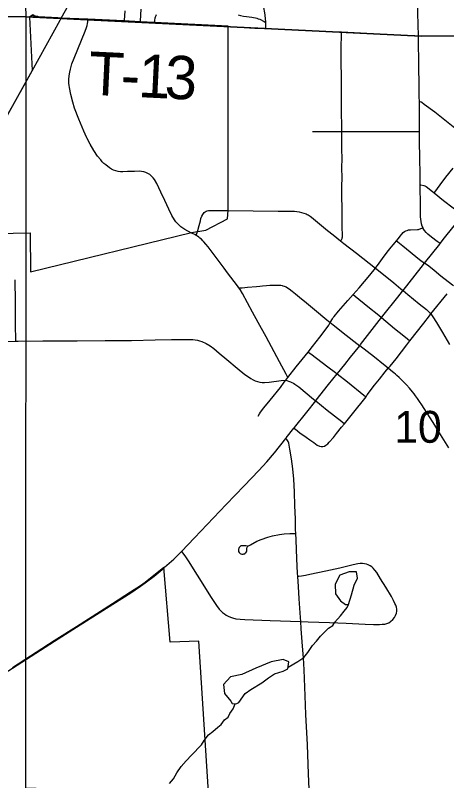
# Model space of a CAD drawing. Extents: x 0 to 34, y -5 to 22.
# Drawn here: x 3.09 to 3.656, y 14.615 to 15.62 of the extents above; entities that cross this region are included whole.
import ezdxf

# ---------------------------------------------------------------- set-up
doc = ezdxf.new("R2010")
doc.units = 0
for name, color, linetype in [('GM_X_City_Street', 7, 'Continuous'), ('GM_X_Corporation', 7, 'Continuous'), ('GM_X_County_Road', 7, 'Continuous'), ('GM_X_Minor_Lake', 7, 'Continuous'), ('GM_X_Minor_River', 7, 'Continuous'), ('GM_X_Section', 7, 'Continuous'), ('GM_X_Section_Text', 7, 'Continuous'), ('GM_X_State_Route', 7, 'Continuous'), ('GM_X_Township_Road', 7, 'Continuous'), ('GM_X_Township_Road_Text', 7, 'Continuous')]:
    doc.layers.add(name, color=color, linetype=linetype)

msp = doc.modelspace()

# ---------------------------------------------------------------- linework, layer by layer
at = {"layer": 'GM_X_City_Street'}
for points in [[(3.4191, 15.6022), (3.4191, 15.6043), (3.4191, 15.6081), (3.419, 15.6103), (3.419, 15.6115), (3.4187, 15.6143), (3.4181, 15.6203), (3.4162, 15.6325), (3.4142, 15.6442), (3.4121, 15.6568), (3.4104, 15.6677), (3.4099, 15.6736), (3.4097, 15.6784)], [(3.2548, 15.6277), (3.2543, 15.6125), (3.2542, 15.6106)], [(3.2334, 15.6117), (3.2334, 15.6128), (3.2342, 15.6256)], [(3.2733, 15.6097), (3.2734, 15.6111), (3.2735, 15.6128), (3.274, 15.6164), (3.2743, 15.6177), (3.275, 15.6195), (3.2756, 15.6205)], [(3.3827, 15.62), (3.386, 15.6192), (3.3896, 15.6185), (3.3936, 15.618), (3.3972, 15.6176), (3.4009, 15.6171), (3.4029, 15.6167), (3.4056, 15.6162), (3.4072, 15.6157), (3.4092, 15.6151), (3.4111, 15.6143), (3.4168, 15.6114), (3.419, 15.6103)], [(3.5173, 15.3235), (3.5177, 15.3241), (3.5184, 15.3251), (3.5188, 15.3258), (3.5191, 15.3267), (3.5193, 15.3278), (3.5195, 15.329), (3.5194, 15.344), (3.5192, 15.3673), (3.519, 15.3808), (3.5189, 15.395), (3.5191, 15.4069), (3.5189, 15.4191), (3.5191, 15.4323), (3.519, 15.4436), (3.5188, 15.4552), (3.5188, 15.4651), (3.5188, 15.4671), (3.5187, 15.476), (3.5186, 15.4909), (3.5185, 15.5064), (3.5183, 15.5236), (3.5182, 15.5435), (3.5181, 15.5528), (3.518, 15.5713), (3.5181, 15.5775), (3.5184, 15.5939), (3.5185, 15.5977)], [(3.6206, 15.5065), (3.6214, 15.5064), (3.6224, 15.5062), (3.6231, 15.506), (3.6239, 15.5055), (3.6271, 15.5031), (3.6407, 15.4928), (3.6651, 15.4737), (3.6741, 15.4666), (3.6828, 15.4597), (3.6922, 15.4523), (3.6965, 15.449), (3.7073, 15.4403), (3.7212, 15.429), (3.7284, 15.4232), (3.7294, 15.4224)], [(3.4803, 15.4673), (3.4941, 15.4673), (3.5145, 15.4671), (3.5188, 15.4671), (3.5244, 15.4671), (3.5477, 15.4672), (3.5728, 15.4672), (3.5932, 15.4671), (3.6119, 15.4672), (3.6165, 15.4671), (3.6209, 15.4671)], [(3.64, 15.3866), (3.6407, 15.3876), (3.6477, 15.3972), (3.6555, 15.4072), (3.6651, 15.4191)], [(3.6217, 15.3972), (3.6226, 15.397), (3.6266, 15.3963), (3.6276, 15.396), (3.6287, 15.3956), (3.6296, 15.3951), (3.6377, 15.3885), (3.64, 15.3866), (3.6524, 15.3765), (3.6651, 15.3668), (3.6693, 15.3633), (3.6758, 15.3582), (3.6773, 15.357)], [(3.3696, 15.3635), (3.4351, 15.3628), (3.4506, 15.3626), (3.4568, 15.3624), (3.463, 15.3617), (3.466, 15.361), (3.469, 15.3601), (3.4719, 15.3591), (3.4735, 15.3583), (3.4747, 15.3577), (3.4772, 15.356), (3.4788, 15.3548), (3.5002, 15.3373), (3.5073, 15.3315), (3.5173, 15.3235), (3.5215, 15.3202), (3.538, 15.3073), (3.5629, 15.2877), (3.5646, 15.2864), (3.5869, 15.2687), (3.5964, 15.2609), (3.5992, 15.2585)], [(3.5629, 15.2877), (3.5636, 15.2888), (3.5656, 15.2915), (3.5745, 15.3036), (3.58, 15.3109), (3.5838, 15.3155), (3.5865, 15.3187), (3.5885, 15.3209), (3.5907, 15.3236), (3.5931, 15.3267), (3.5955, 15.3299), (3.5977, 15.3326), (3.5995, 15.3346), (3.6013, 15.336), (3.6029, 15.3368), (3.6046, 15.3374), (3.6065, 15.3379), (3.6088, 15.3382), (3.618, 15.3384), (3.6196, 15.3386), (3.6225, 15.3397), (3.6254, 15.3407)], [(3.5907, 15.3236), (3.5924, 15.3223), (3.5991, 15.317), (3.6208, 15.2993), (3.6274, 15.2942)], [(3.5037, 15.2165), (3.5065, 15.2213), (3.5076, 15.2229), (3.5086, 15.2243), (3.5145, 15.2314), (3.5267, 15.2452), (3.5339, 15.2533), (3.5417, 15.2622), (3.5555, 15.2786), (3.5629, 15.2877)], [(3.0908, 15.1919), (3.0907, 15.1974), (3.0905, 15.2095), (3.0904, 15.243), (3.0902, 15.2727)], [(3.3838, 15.2619), (3.3882, 15.2622), (3.3948, 15.2628), (3.4067, 15.2639), (3.4111, 15.2644), (3.4147, 15.2647), (3.42, 15.2652), (3.4242, 15.2655), (3.4265, 15.2656), (3.4284, 15.2656), (3.4311, 15.2657), (3.4343, 15.2657), (3.4376, 15.2655), (3.4389, 15.2654), (3.4403, 15.2651), (3.4415, 15.2648), (3.443, 15.2643), (3.4443, 15.2638), (3.4456, 15.2631), (3.4475, 15.2621), (3.4497, 15.2607), (3.4535, 15.2577), (3.458, 15.2541), (3.4633, 15.2497), (3.4723, 15.2422), (3.4829, 15.2335), (3.4992, 15.2202), (3.5037, 15.2165), (3.5094, 15.212), (3.5207, 15.2029), (3.5423, 15.1859)], [(3.5796, 15.1566), (3.5823, 15.1594), (3.5901, 15.1689), (3.604, 15.1871), (3.6081, 15.1924), (3.6263, 15.2157), (3.6337, 15.2252), (3.6358, 15.2277), (3.6569, 15.2543)], [(3.5992, 15.2585), (3.6055, 15.2534), (3.6204, 15.2412), (3.6299, 15.2335), (3.6328, 15.2309), (3.635, 15.2287), (3.6358, 15.2277), (3.6366, 15.2267), (3.6382, 15.2241), (3.6432, 15.2164), (3.6511, 15.2032), (3.6602, 15.1875)], [(3.5339, 15.2533), (3.5365, 15.251), (3.5529, 15.2373), (3.5673, 15.2261), (3.5711, 15.2231)], [(3.4091, 15.0938), (3.4107, 15.0969), (3.4119, 15.0987), (3.4164, 15.1044), (3.4247, 15.1147), (3.4382, 15.1313), (3.4433, 15.1382), (3.4453, 15.1407), (3.4481, 15.1443), (3.459, 15.1582), (3.4708, 15.1727), (3.4748, 15.1778), (3.4804, 15.185), (3.4898, 15.1974), (3.5007, 15.2117), (3.5018, 15.2132), (3.5026, 15.2146), (3.5037, 15.2165)], [(3.5711, 15.2231), (3.5881, 15.2087), (3.6002, 15.1989), (3.605, 15.195), (3.6081, 15.1924)], [(3.4748, 15.1778), (3.4783, 15.1752), (3.5005, 15.1585), (3.5103, 15.1509), (3.5127, 15.149)], [(3.5224, 15.0837), (3.5365, 15.1012), (3.5473, 15.1148), (3.5506, 15.1192), (3.5522, 15.1214), (3.5619, 15.1341), (3.5682, 15.1423), (3.5755, 15.1518), (3.5796, 15.1566)], [(3.5127, 15.149), (3.5263, 15.1385), (3.5479, 15.1213), (3.5506, 15.1192)], [(3.4845, 15.1138), (3.4994, 15.1017), (3.5187, 15.0866), (3.5224, 15.0837)], [(3.456, 15.078), (3.4578, 15.0765), (3.4637, 15.0717), (3.4719, 15.066), (3.4769, 15.0626), (3.4819, 15.059), (3.4866, 15.0556), (3.4895, 15.0542), (3.4917, 15.0538), (3.4938, 15.0538), (3.4959, 15.0544), (3.498, 15.0556), (3.5003, 15.0573), (3.5024, 15.0594), (3.5079, 15.0658), (3.5117, 15.0708), (3.5185, 15.0791), (3.5224, 15.0837)], [(3.4766, 14.5941), (3.4752, 14.6244), (3.4736, 14.6624), (3.4717, 14.7021), (3.4708, 14.7269), (3.4692, 14.761), (3.4683, 14.7765), (3.4672, 14.792), (3.4656, 14.8148), (3.4649, 14.824), (3.4646, 14.8295), (3.4629, 14.8538), (3.4619, 14.87), (3.4611, 14.8832), (3.4608, 14.8878), (3.4599, 14.9065), (3.4587, 14.9313), (3.4583, 14.9397), (3.4581, 14.9451), (3.4578, 14.9591), (3.4573, 14.9759), (3.4567, 14.9945), (3.4557, 15.0109), (3.4544, 15.0245), (3.4527, 15.0376), (3.4506, 15.0505), (3.4491, 15.0581), (3.4487, 15.0593), (3.4482, 15.0606), (3.4475, 15.0616), (3.4465, 15.0628), (3.4451, 15.0644)], [(3.3949, 14.9229), (3.393, 14.9233), (3.3908, 14.9236), (3.389, 14.9237), (3.3877, 14.9236), (3.3863, 14.9233), (3.3854, 14.9227), (3.3846, 14.9219), (3.384, 14.9212), (3.3836, 14.9202), (3.3833, 14.9192), (3.3832, 14.9182), (3.3832, 14.9172), (3.3834, 14.916), (3.3839, 14.9149), (3.3845, 14.9141), (3.3854, 14.9134), (3.3863, 14.9129), (3.3874, 14.9126), (3.3885, 14.9125), (3.3895, 14.9126), (3.3904, 14.9128), (3.3913, 14.9132), (3.3919, 14.9137), (3.3928, 14.9145), (3.3936, 14.9156), (3.394, 14.9165), (3.3942, 14.9175), (3.3943, 14.9208), (3.3945, 14.9217), (3.3949, 14.9224), (3.3953, 14.923), (3.3988, 14.925), (3.4071, 14.9294), (3.4129, 14.9319), (3.4217, 14.935), (3.4278, 14.9366), (3.437, 14.9384), (3.4432, 14.9391), (3.4504, 14.9395), (3.4564, 14.9397), (3.4583, 14.9397)], [(3.3084, 14.916), (3.3127, 14.9102), (3.317, 14.904), (3.3291, 14.8848), (3.3475, 14.8559), (3.3543, 14.8454), (3.358, 14.8405), (3.3601, 14.8383), (3.3623, 14.8362), (3.3646, 14.8343), (3.3671, 14.8325), (3.3698, 14.831), (3.3725, 14.8298), (3.3754, 14.8289), (3.3798, 14.8278), (3.3854, 14.8271), (3.3914, 14.8269), (3.4248, 14.8254), (3.4649, 14.824), (3.4746, 14.8237), (3.5027, 14.8229), (3.5244, 14.8219), (3.5493, 14.8207), (3.5603, 14.8203), (3.5683, 14.8204), (3.5719, 14.8205), (3.5751, 14.8209), (3.5778, 14.8215), (3.5805, 14.8226), (3.5828, 14.8242), (3.5859, 14.8269), (3.5879, 14.8295), (3.5893, 14.8321), (3.5904, 14.835), (3.5909, 14.8376), (3.5909, 14.8402), (3.5904, 14.843), (3.5896, 14.8456), (3.5884, 14.848), (3.5866, 14.8519), (3.5839, 14.8569), (3.5764, 14.8691), (3.5695, 14.8804), (3.5646, 14.8884), (3.5623, 14.8915), (3.5598, 14.8944), (3.5581, 14.896), (3.5559, 14.8973), (3.5535, 14.8985), (3.5511, 14.8993), (3.5487, 14.8999), (3.5459, 14.9002), (3.5431, 14.9002), (3.5397, 14.9), (3.5337, 14.8986), (3.516, 14.8944), (3.498, 14.8903), (3.477, 14.8858), (3.4711, 14.8847), (3.4658, 14.8838), (3.4626, 14.8834), (3.4611, 14.8832)]]:
    msp.add_lwpolyline(points, dxfattribs=at)
msp.add_lwpolyline([(2.1, 15.6177), (2.1, 15.3638), (2.1133, 14.5841), (3.104, 14.6056), (3.1044, 15.6177)], close=True, dxfattribs=at)
at = {"layer": 'GM_X_Corporation'}
for points in [[(2.9981, 15.3319), (3.1097, 15.3342), (3.1101, 15.283), (3.3215, 15.3344), (3.3404, 15.3375), (3.3688, 15.3524), (3.3694, 15.3641), (3.3695, 15.6054), (3.2731, 15.6102), (3.254, 15.6112), (3.2327, 15.6123), (3.1852, 15.6144), (3.15, 15.6159), (3.146, 15.6163), (3.1208, 15.6177), (3.1203, 15.6177), (3.1198, 15.6178), (3.1188, 15.6179), (3.1165, 15.6184), (3.1156, 15.6187), (3.1147, 15.6191), (3.1131, 15.6201), (3.1088, 15.6173), (3.1122, 15.5472), (2.9904, 15.3289)], [(3.3438, 14.6005), (3.3313, 14.7985), (3.2934, 14.7972), (3.2852, 14.8952), (3.2722, 14.8844), (3.2605, 14.8754), (3.2544, 14.8712), (3.2415, 14.8626), (3.2179, 14.8475), (3.1705, 14.8173), (3.1414, 14.7989), (3.0864, 14.7636)]]:
    msp.add_lwpolyline(points, dxfattribs=at)
at = {"layer": 'GM_X_County_Road'}
for p, q in [((3.6274, 15.2942), (3.6473, 15.3192)), ((3.6473, 15.3192), (3.6479, 15.32)), ((3.5429, 15.1867), (3.5435, 15.1875)), ((3.3077, 14.9154), (3.3084, 14.916))]:
    msp.add_line(p, q, dxfattribs=at)
for points in [[(3.6193, 15.5928), (3.6173, 15.6675), (3.617, 15.6947)], [(3.6206, 15.5065), (3.6205, 15.5125), (3.6202, 15.5311), (3.62, 15.5496), (3.6198, 15.5588), (3.6194, 15.5833), (3.6193, 15.5928)], [(3.6209, 15.4671), (3.6208, 15.479), (3.6207, 15.4882), (3.6207, 15.5002), (3.6206, 15.5065)], [(3.6217, 15.3972), (3.6216, 15.4109), (3.6213, 15.4325), (3.6209, 15.4542), (3.6209, 15.4671)], [(3.6254, 15.3407), (3.6244, 15.3428), (3.6235, 15.3459), (3.6229, 15.349), (3.6223, 15.3552), (3.6221, 15.3614), (3.622, 15.3738), (3.6218, 15.3924), (3.6217, 15.3972)], [(3.6479, 15.32), (3.6538, 15.3275), (3.6773, 15.357)], [(3.6479, 15.32), (3.644, 15.3228), (3.6365, 15.3284), (3.6317, 15.3324), (3.6294, 15.3347), (3.6274, 15.3372), (3.6258, 15.3399), (3.6254, 15.3407)], [(3.5986, 15.2578), (3.5992, 15.2585), (3.6229, 15.2886), (3.6274, 15.2942)], [(3.6653, 15.2645), (3.6641, 15.2655), (3.649, 15.2774), (3.6402, 15.2848), (3.6329, 15.2903), (3.6274, 15.2942)], [(3.5717, 15.2238), (3.5728, 15.2253), (3.5922, 15.2496), (3.5986, 15.2578)], [(3.5435, 15.1875), (3.5556, 15.2032), (3.5711, 15.2231), (3.5717, 15.2238)], [(3.0908, 15.1919), (3.0939, 15.1919), (3.1263, 15.1923), (3.1394, 15.1923), (3.1713, 15.1924), (3.2081, 15.1929), (3.2428, 15.193), (3.2736, 15.1937), (3.2954, 15.1942), (3.3085, 15.1944), (3.3171, 15.1943), (3.3233, 15.1941), (3.3293, 15.1932), (3.3322, 15.1924), (3.335, 15.1914), (3.3406, 15.1889), (3.3458, 15.1858), (3.3506, 15.1822), (3.3577, 15.1764), (3.3678, 15.168), (3.3816, 15.1564), (3.3916, 15.1483), (3.3962, 15.1451), (3.3995, 15.1429), (3.4023, 15.1413), (3.4052, 15.1401), (3.4083, 15.1391), (3.4112, 15.1384), (3.4142, 15.138), (3.4173, 15.1379), (3.4236, 15.1383), (3.439, 15.1404), (3.4453, 15.1407)], [(3.0273, 15.1915), (3.0452, 15.1918), (3.0908, 15.1919)], [(3.5304, 15.171), (3.5423, 15.1859), (3.5429, 15.1867)], [(3.5133, 15.1498), (3.5229, 15.1616), (3.5304, 15.171)], [(3.4852, 15.1146), (3.5015, 15.1351), (3.5127, 15.149), (3.5133, 15.1498)], [(3.4453, 15.1407), (3.4467, 15.1403), (3.4489, 15.1397), (3.4516, 15.1388), (3.4533, 15.138), (3.4554, 15.1369), (3.4572, 15.1357), (3.4622, 15.132), (3.4817, 15.1161), (3.4845, 15.1138)], [(3.4566, 15.0788), (3.4727, 15.0988), (3.4845, 15.1138), (3.4852, 15.1146)], [(3.4456, 15.0651), (3.456, 15.078), (3.4566, 15.0788)], [(3.3084, 14.916), (3.3256, 14.934), (3.3671, 14.9778), (3.3907, 15.0024), (3.41, 15.0225), (3.4205, 15.0338), (3.4303, 15.0457), (3.4451, 15.0644), (3.4456, 15.0651)], [(3.2861, 14.8954), (3.2981, 14.9062), (3.3077, 14.9154)], [(3.0274, 14.7258), (3.0523, 14.7416), (3.0866, 14.7631), (3.1416, 14.7983), (3.1707, 14.8168), (3.2181, 14.847), (3.2417, 14.862), (3.2546, 14.8707), (3.2607, 14.8748), (3.2724, 14.8838), (3.2854, 14.8947), (3.2861, 14.8954)]]:
    msp.add_lwpolyline(points, dxfattribs=at)
at = {"layer": 'GM_X_Minor_Lake'}
for points in [[(3.5277, 14.8465), (3.5317, 14.859), (3.535, 14.872), (3.5392, 14.8811), (3.5383, 14.8895), (3.5285, 14.8894), (3.5164, 14.8851), (3.51, 14.8733), (3.5105, 14.8604), (3.517, 14.8513)], [(3.517, 14.8513), (3.5237, 14.8464), (3.5277, 14.8465)], [(3.3837, 14.7181), (3.392, 14.7299), (3.3995, 14.7349), (3.4139, 14.7438), (3.4225, 14.7503), (3.4305, 14.7557), (3.4418, 14.7592), (3.4479, 14.7623), (3.4493, 14.7714), (3.4417, 14.7744), (3.4262, 14.7712), (3.4058, 14.7631), (3.3876, 14.7546), (3.3725, 14.7514), (3.3634, 14.7415), (3.365, 14.7297), (3.3731, 14.7195)], [(3.3731, 14.7195), (3.375, 14.7168), (3.3778, 14.7162), (3.3812, 14.7168), (3.3837, 14.7181)]]:
    msp.add_lwpolyline(points, dxfattribs=at)
at = {"layer": 'GM_X_Minor_River'}
for points in [[(3.4482, 14.7645), (3.4609, 14.7719), (3.4688, 14.777), (3.4744, 14.7836), (3.4803, 14.7928), (3.4855, 14.7982), (3.4907, 14.8048), (3.5012, 14.8153), (3.5068, 14.8188), (3.5098, 14.8234), (3.5172, 14.8316), (3.522, 14.8378), (3.5258, 14.8424), (3.5277, 14.8465)], [(3.2927, 14.6115), (3.2979, 14.6177), (3.3023, 14.6258), (3.3079, 14.6339), (3.3146, 14.6412), (3.3217, 14.649), (3.3347, 14.6625), (3.3381, 14.6679), (3.344, 14.6757), (3.3496, 14.68), (3.356, 14.6854), (3.3605, 14.6889), (3.3649, 14.6951), (3.3694, 14.6986), (3.372, 14.7036), (3.3761, 14.7098), (3.3786, 14.7164)]]:
    msp.add_lwpolyline(points, dxfattribs=at)
at = {"layer": 'GM_X_Section'}
for points in [[(4.1248, 16.5469), (4.1342, 15.5936), (3.6228, 15.592), (3.1044, 15.6177), (3.0783, 16.5351), (3.1825, 16.5361), (3.5929, 16.5408), (3.9967, 16.5453)], [(3.1044, 15.6177), (3.6228, 15.592), (4.1342, 15.5936), (4.1458, 14.5934), (3.5359, 14.5917), (3.104, 14.6056)]]:
    msp.add_lwpolyline(points, close=True, dxfattribs=at)
at = {"layer": 'GM_X_State_Route'}
for points in [[(3.1503, 15.6156), (3.2177, 15.7357), (3.2353, 15.7649), (3.2508, 15.7881), (3.258, 15.7986), (3.2672, 15.8107), (3.2754, 15.8208), (3.2829, 15.83), (3.2932, 15.8419), (3.3015, 15.8507), (3.3106, 15.86), (3.3189, 15.8684), (3.3294, 15.8782), (3.3396, 15.8872), (3.3498, 15.8961), (3.3635, 15.907), (3.3721, 15.9138), (3.3818, 15.9208), (3.3938, 15.9293)], [(3.1124, 15.5466), (3.149, 15.6133), (3.1503, 15.6156)], [(2.9906, 15.3283), (3.0799, 15.4886), (3.1124, 15.5466)]]:
    msp.add_lwpolyline(points, dxfattribs=at)
at = {"layer": 'GM_X_Township_Road'}
msp.add_line((3.2334, 15.6117), (3.2542, 15.6106), dxfattribs=at)
for points in [[(3.1133, 15.6196), (3.1149, 15.6185), (3.1167, 15.6178), (3.119, 15.6173), (3.121, 15.6172), (3.1503, 15.6156)], [(3.1503, 15.6156), (3.121, 15.6172), (3.119, 15.6173), (3.1167, 15.6178), (3.1149, 15.6185), (3.1133, 15.6196)], [(3.1503, 15.6156), (3.1569, 15.6152), (3.1827, 15.614), (3.1854, 15.6139)], [(3.1608, 15.5276), (3.1605, 15.5304), (3.1604, 15.5354), (3.1607, 15.5402), (3.1616, 15.5449), (3.1625, 15.5488), (3.1646, 15.556), (3.1674, 15.5633), (3.1817, 15.5989), (3.1835, 15.6036), (3.1845, 15.6064), (3.1851, 15.6088), (3.1854, 15.611), (3.1854, 15.6139)], [(3.1854, 15.6139), (3.2325, 15.6118), (3.2334, 15.6117)], [(3.2542, 15.6106), (3.2635, 15.6101), (3.2733, 15.6097)], [(3.2733, 15.6097), (3.3224, 15.6075), (3.3595, 15.6056), (3.3697, 15.6049)], [(3.3697, 15.6049), (3.4045, 15.6029), (3.4191, 15.6022)], [(3.4191, 15.6022), (3.4543, 15.6005), (3.4824, 15.5992), (3.5157, 15.5978), (3.5185, 15.5977)], [(3.5185, 15.5977), (3.6021, 15.5935), (3.6146, 15.593), (3.6193, 15.5928)], [(3.1837, 15.4597), (3.1802, 15.4675), (3.1737, 15.4832), (3.1681, 15.4978), (3.1655, 15.5058), (3.1629, 15.5156), (3.1612, 15.5248), (3.1608, 15.5276)], [(3.3217, 15.3339), (3.3128, 15.3386), (3.3102, 15.3403), (3.3076, 15.3422), (3.3053, 15.3442), (3.303, 15.3464), (3.3009, 15.3488), (3.2991, 15.3513), (3.2958, 15.3567), (3.2917, 15.3651), (3.2865, 15.3764), (3.2812, 15.3876), (3.2758, 15.3987), (3.2728, 15.404), (3.271, 15.4064), (3.2689, 15.4086), (3.2666, 15.4105), (3.2642, 15.4122), (3.2615, 15.4135), (3.2587, 15.4143), (3.2557, 15.4148), (3.2527, 15.415), (3.2467, 15.4148), (3.2375, 15.4145), (3.2313, 15.4142), (3.2282, 15.4143), (3.2252, 15.4147), (3.2221, 15.4154), (3.2192, 15.4165), (3.2164, 15.4179), (3.2137, 15.4195), (3.2089, 15.4233), (3.2066, 15.4253), (3.2044, 15.4275), (3.2023, 15.4298), (3.1983, 15.4346), (3.1932, 15.4424), (3.1884, 15.4505), (3.1841, 15.4588), (3.1837, 15.4597)], [(3.3277, 15.3307), (3.3297, 15.3372), (3.3317, 15.3439), (3.3331, 15.3498), (3.3339, 15.3528), (3.3352, 15.3559), (3.3363, 15.3582), (3.3373, 15.3596), (3.3382, 15.3607), (3.3393, 15.3615), (3.3408, 15.3625), (3.3422, 15.3629), (3.344, 15.3633), (3.3476, 15.3636), (3.3599, 15.3636), (3.3696, 15.3635)], [(3.3277, 15.3307), (3.3258, 15.3318), (3.3217, 15.3339)], [(3.3378, 15.3223), (3.3365, 15.3237), (3.3344, 15.3258), (3.3326, 15.3273), (3.3312, 15.3285), (3.3293, 15.3298), (3.3277, 15.3307)], [(3.3838, 15.2619), (3.3819, 15.2646), (3.3686, 15.2818), (3.3642, 15.288), (3.3552, 15.3002), (3.3434, 15.3156), (3.3402, 15.3195), (3.3378, 15.3223)], [(3.4481, 15.1443), (3.4458, 15.1488), (3.4372, 15.1651), (3.4196, 15.1977), (3.4092, 15.2166), (3.4017, 15.23), (3.3885, 15.2544), (3.3854, 15.2596), (3.3838, 15.2619)], [(3.5796, 15.1566), (3.5737, 15.1613), (3.5615, 15.1709), (3.5423, 15.1859)], [(3.6592, 15.0519), (3.6483, 15.0694), (3.6408, 15.0816), (3.6347, 15.0913), (3.6269, 15.1036), (3.6238, 15.1086), (3.6209, 15.113), (3.6181, 15.1169), (3.6156, 15.1204), (3.6138, 15.1228), (3.6117, 15.1254), (3.6076, 15.1304), (3.6036, 15.1347), (3.6001, 15.1382), (3.5973, 15.1411), (3.5939, 15.1443), (3.5912, 15.1468), (3.5891, 15.1487), (3.587, 15.1506), (3.5833, 15.1535), (3.5796, 15.1566)]]:
    msp.add_lwpolyline(points, dxfattribs=at)

# ---------------------------------------------------------------- texts
at = {"layer": 'GM_X_Section_Text'}
msp.add_text('10', height=0.04186, rotation=0, dxfattribs=at).set_placement((3.5877, 15.0587))
at = {"layer": 'GM_X_Township_Road_Text'}
for s, rotation, p in [('T', 357.2559, (3.1853, 15.5155)), ('1', 357.2126, (3.2507, 15.5123)), ('3', 357.1956, (3.2854, 15.5106)), ('-', 357.2292, (3.2276, 15.5134))]:
    msp.add_text(s, height=0.0568, rotation=rotation, dxfattribs=at).set_placement(p)

doc.saveas('drawing.dxf')
